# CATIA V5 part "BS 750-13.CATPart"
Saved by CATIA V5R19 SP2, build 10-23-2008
Part number: BS 750-13
Bounding box of the stored display mesh (mm): x -22.494 to 22.494, y -22.494 to 22.494, z 0 to 58
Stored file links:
  C:\Users\Bora\Desktop\3D Katı model\BS serisi\BS 750\BS 750-13.CATPart
  C:\Program Files\Dassault Systemes\B19\intel_a\reffiles\standard\MetricThickPitch.txt
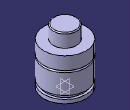
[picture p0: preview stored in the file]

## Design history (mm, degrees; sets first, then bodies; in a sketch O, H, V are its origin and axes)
Body1 (main body)
  Sketch1 on yz-plane, origin (0, 0, 0), H (0, 1, 0), V (0, 0, 1)
    point P3 (12.5, 57)
    point P5 (12.5, 57)
    point P7 (22.5, 30.5)
    point P8 (22.5, 28.5)
    point P12 (22.5, 28.5)
    point P13 (22.5, 30.5)
    line L1 (22.5, 0) -> (22.5, 4)
    line L2 (12.5, 57) -> (12.5, 44)
    arc A1 centre (11.5, 57) radius 1 from (12.5, 57) to (11.5, 58) ccw
    arc A2 centre (22.5, 29.5) radius 1 from (22.5, 30.5) to (22.5, 28.5) ccw
    line L3 (20, 7.5) -> (20, 4)
    line L4 (22.5, 7.5) -> (22.5, 28.5)
    line L5 (22.5, 30.5) -> (22.5, 44)
    line L6 (11.5, 58) -> (0, 58)
    point P15 (0, 58)
    line L7 (12.5, 44) -> (22.5, 44)
    line L8 (0, 0) -> (22.5, 0)
    line L9 (20, 7.5) -> (22.5, 7.5)
    line L10 (20, 4) -> (22.5, 4)
    tangency: L6 A1
    coincidence: P15 V, P3 P5, P7 P13, P8 P12
    horizontal: L7 H, L8 H, L9 H, L10 H
  Shaft1: profile Sketch1, axis Sketch1.V, angle 360
  Sketch2 on face of Shaft1 from Sketch1.L8, origin (0, 0, 0), H (1, 0, 0), V (0, -1, 0)
    point P1 (10, 0)
    distance P1 V = 10
  Hole1: placed by Sketch2, at (10, 0, 0) direction (0, 0, 1), diameter 6.647, depth 4, threaded "M8", thread diameter 8, thread depth 4, pitch 1.25
  CircPattern1: of Hole1, instances 2, angular step 180, axis from xy-plane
